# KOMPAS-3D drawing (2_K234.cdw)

Views: Вид 1
Referenced files: Чертеж Корпус 4.cdw
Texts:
  Корпус №4
  Проектный 1
  Корпус №2
  Georgia
  Корпус №3
  Лист
  Изм.
  № докум.
  Подп.
  Дата
  Инв. № подл.
  Подп. и дата
  Взам. инв. №
  Инв. № дубл.
  План
  План фонарей. Лит. 4
  РАЗРЕЗ 1-1
  РАЗРЕЗ 2-2
  План 1 этажа
  ISO 02 штриховая линия
  Стили документа
Dimensions and other numbers on the sheet: 2; 3; 4; 5; 6; 1; 7; 8; 9; 10; 11; 12; 13; 14; 19; 21; 23; 24; 25; 26; 15; 17; 18; 22; 27; 20; 1/1; 2/1; 3/1; 4/1; 4/2; 5/1; 6/1; 7/1; 8/1; 12/1; 9/1; 10/1; 11/1; 16; 1:1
